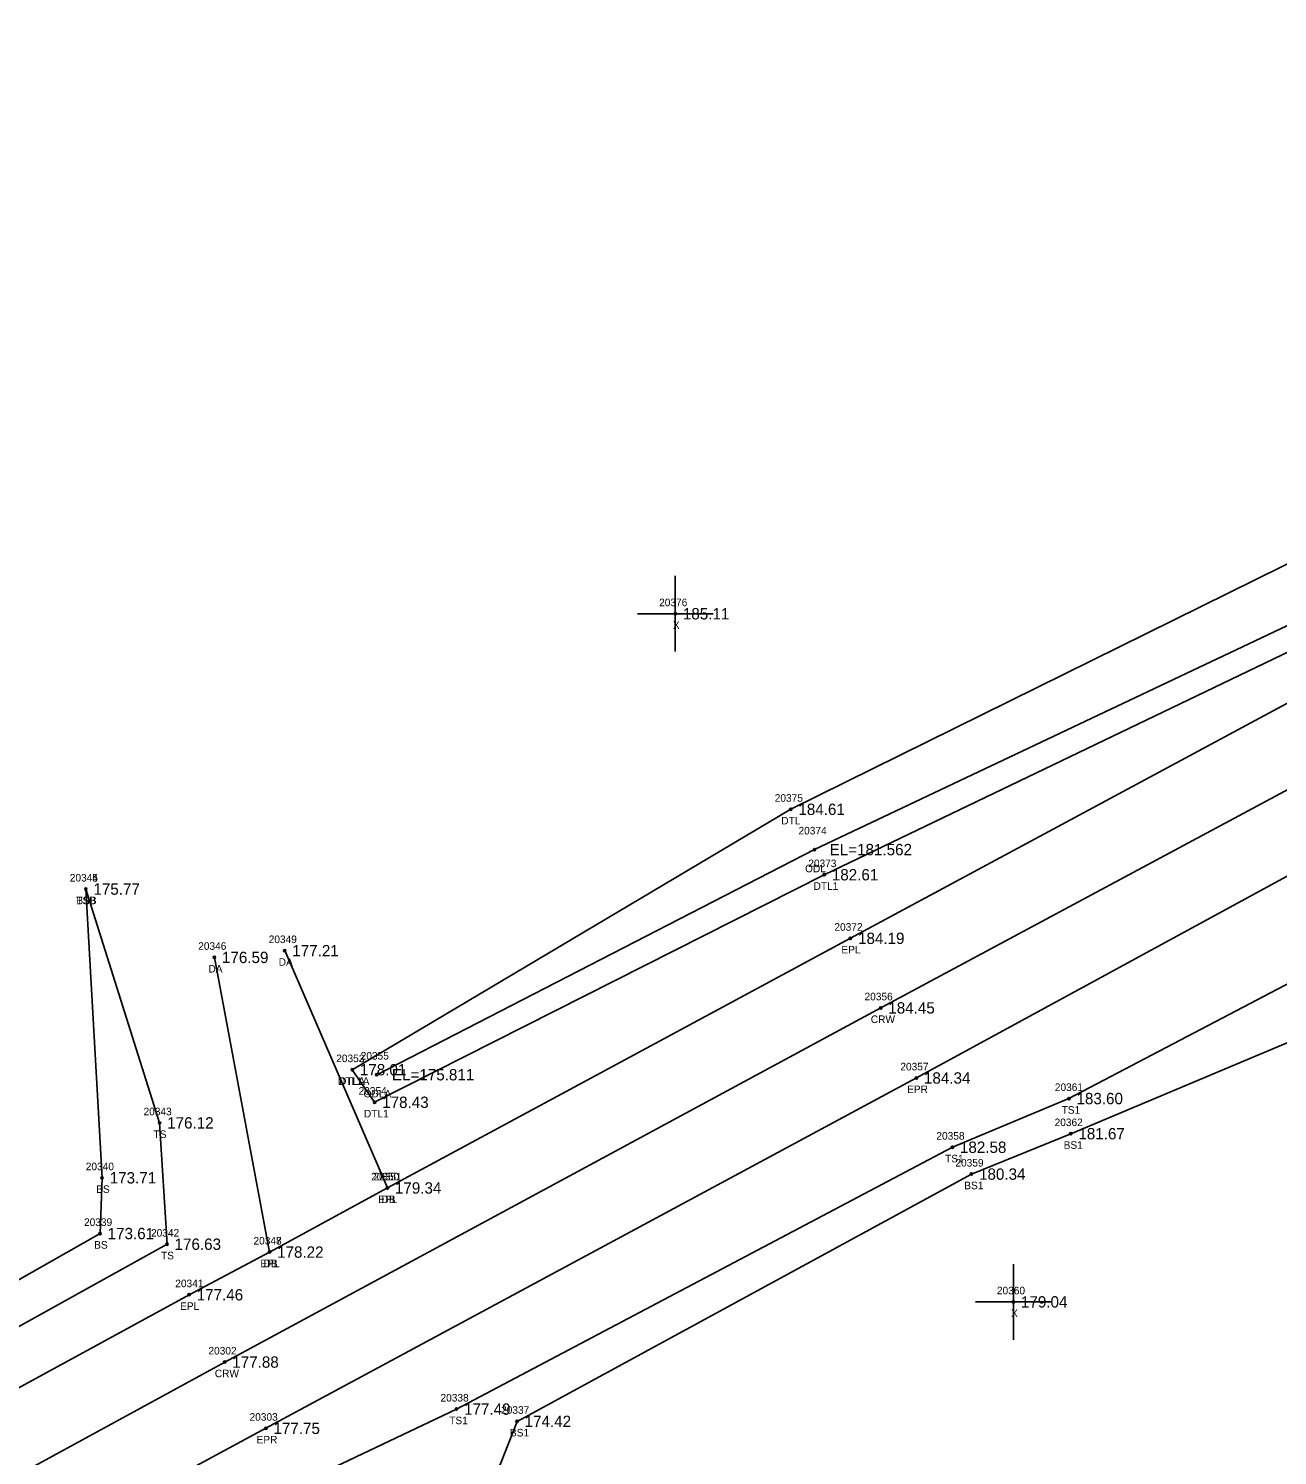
# Model space of a CAD drawing. Extents: x 2279528 to 2280976, y 1061373 to 1062235.
# Drawn here: x 2280628.7 to 2280793.7, y 1062015.3 to 1062203.8 of the extents above; entities that cross this region are included whole.
import ezdxf

# ---------------------------------------------------------------- set-up
doc = ezdxf.new("R2010")
doc.units = 0
for name, color, linetype in [('RD_DTM_BkLn1', 7, 'Continuous'), ('RD_DTM_BkLn2', 7, 'Continuous'), ('RD_DTM_BkLn_txCode', 7, 'Continuous'), ('RD_EX_Driveway', 7, 'Continuous'), ('RD_EX_Driveway_txCode', 7, 'Continuous'), ('RD_EX_H2O', 7, 'Continuous'), ('RD_EX_H2O_txCode', 7, 'Continuous'), ('RD_EX_Misc', 7, 'Continuous'), ('RD_EX_Misc_txCode', 7, 'Continuous'), ('RD_EX_Road', 7, 'Continuous'), ('RD_EX_Road_txCode', 7, 'Continuous'), ('RD_EX_TX_Driveway_ELEV', 7, 'Continuous'), ('RD_EX_TX_H2O_ELEV', 7, 'Continuous'), ('RD_EX_TX_Misc_ELEV', 7, 'Continuous'), ('RD_EX_TX_Road_ELEV', 7, 'Continuous'), ('RD_HC_Survey_ELEV', 7, 'Continuous'), ('RD_HC_Survey_txCode', 7, 'Continuous'), ('RD_SMD_Locator', 7, 'Continuous')]:
    doc.layers.add(name, color=color, linetype=linetype)

msp = doc.modelspace()

# ---------------------------------------------------------------- linework, layer by layer
at = {"layer": 'RD_DTM_BkLn1'}
msp.add_lwpolyline([(2279559.79, 1061433.13), (2279641.23, 1061477.49), (2279727.93, 1061524.84), (2279814.76, 1061571.75), (2279901.26, 1061618.64), (2279982.8, 1061662.56), (2280064.7, 1061706.86), (2280148.08, 1061751.86), (2280234.22, 1061798.46), (2280310.96, 1061840.01), (2280397.69, 1061887.57), (2280487.27, 1061936.5), (2280573.03, 1061983.12), (2280654.64, 1062027.66), (2280741.28, 1062074.45), (2280833.39, 1062123.87), (2280892.52, 1062155.9), (2280939.46, 1062181.85)], dxfattribs=at)
at = {"layer": 'RD_DTM_BkLn2'}
for points in [[(2280244.17, 1061836.72), (2280279.92, 1061859.99), (2280384.06, 1061910.85), (2280474.95, 1061958.02), (2280563.04, 1062001.93), (2280638.18, 1062044.64), (2280638.45, 1062052), (2280636.3, 1062090.14)], [(2280254.15, 1061833.04), (2280297.35, 1061859.31), (2280389.94, 1061901.4), (2280479.75, 1061950.78), (2280565.23, 1061997.82), (2280647.02, 1062043.23), (2280646.04, 1062059.26), (2280636.3, 1062090.14)], [(2280272.88, 1061795.9), (2280297.58, 1061791.78), (2280309.49, 1061810.68), (2280320.64, 1061820.76), (2280406.65, 1061872.9), (2280496.79, 1061919.98), (2280582.43, 1061964.41), (2280663.95, 1062011.32), (2280685.25, 1062021.45), (2280750.74, 1062056.04), (2280766.13, 1062062.47), (2280799.22, 1062079.83)], [(2280270.02, 1061790.74), (2280279.94, 1061788.98), (2280298.7, 1061789.36), (2280312.74, 1061804.74), (2280323.13, 1061815.81), (2280411.42, 1061866.03), (2280499.93, 1061915.08), (2280584.56, 1061957.49), (2280666.91, 1062006.18), (2280674.46, 1062011.72), (2280685.18, 1062009.25), (2280689.93, 1062011.32), (2280693.25, 1062019.83), (2280753.26, 1062052.49), (2280766.38, 1062057.83), (2280800.29, 1062072.08)]]:
    msp.add_lwpolyline(points, dxfattribs=at)
at = {"layer": 'RD_EX_Driveway'}
for p, q in [((2280653.28, 1062081.12), (2280660.56, 1062042.19)), ((2280662.57, 1062082.01), (2280676.12, 1062050.66))]:
    msp.add_line(p, q, dxfattribs=at)
at = {"layer": 'RD_EX_H2O'}
for points in [[(2280671.49, 1062066.28), (2280729.4, 1062100.68), (2280823.37, 1062147.12), (2280881.44, 1062177.57), (2280928.45, 1062203.82)], [(2280674.72, 1062065.62), (2280732.53, 1062095.36), (2280825.67, 1062139.48), (2280884.68, 1062169.76), (2280932.06, 1062197.02)], [(2280671.49, 1062066.28), (2280674.44, 1062061.98), (2280733.82, 1062092.04), (2280826.76, 1062136.68), (2280885.73, 1062168.41), (2280932.89, 1062194.62)]]:
    msp.add_lwpolyline(points, dxfattribs=at)
at = {"layer": 'RD_EX_Misc'}
for p, q in [((2280714.15, 1062121.51), (2280714.15, 1062131.51)), ((2280709.15, 1062126.51), (2280719.15, 1062126.51)), ((2280758.8, 1062030.61), (2280758.8, 1062040.61)), ((2280753.8, 1062035.61), (2280763.8, 1062035.61))]:
    msp.add_line(p, q, dxfattribs=at)
at = {"layer": 'RD_EX_Road'}
for points in [[(2279554.31, 1061441.46), (2279636.61, 1061486.51), (2279673.46, 1061506.76), (2279683.06, 1061512.21), (2279723.14, 1061533.54), (2279809.28, 1061580.29), (2279896.91, 1061627.91), (2279977.07, 1061671.02), (2280059.64, 1061715.57), (2280142.91, 1061760.72), (2280228.83, 1061807.06), (2280306.04, 1061849.18), (2280392.98, 1061896.71), (2280482.82, 1061945.75), (2280567.83, 1061991.78), (2280649.94, 1062036.55), (2280660.56, 1062042.19), (2280676.12, 1062050.66), (2280737.28, 1062083.64), (2280828.54, 1062132.77), (2280887.86, 1062164.61), (2280934.91, 1062190.9)], [(2280403.05, 1061879.04), (2280492, 1061927.92), (2280577.25, 1061974.17), (2280660.08, 1062018.91), (2280745.99, 1062065.19), (2280838.21, 1062115.39), (2280896.66, 1062146.92), (2280943.94, 1062172.8)]]:
    msp.add_lwpolyline(points, dxfattribs=at)
at = {"layer": 'RD_SMD_Locator'}
for centre in [(2280714.15, 1062126.51), (2280729.4, 1062100.68), (2280732.53, 1062095.36), (2280733.82, 1062092.04), (2280636.3, 1062090.14), (2280636.3, 1062090.14), (2280737.28, 1062083.64), (2280653.28, 1062081.12), (2280662.57, 1062082.01), (2280741.28, 1062074.45), (2280671.49, 1062066.28), (2280671.49, 1062066.28), (2280674.72, 1062065.62), (2280745.99, 1062065.19), (2280674.44, 1062061.98), (2280766.13, 1062062.47), (2280646.04, 1062059.26), (2280766.38, 1062057.83), (2280750.74, 1062056.04), (2280638.45, 1062052), (2280753.26, 1062052.49), (2280676.12, 1062050.66), (2280676.12, 1062050.66), (2280638.18, 1062044.64), (2280647.02, 1062043.23), (2280660.56, 1062042.19), (2280660.56, 1062042.19), (2280649.94, 1062036.55), (2280758.8, 1062035.61), (2280654.64, 1062027.66), (2280685.25, 1062021.45), (2280660.08, 1062018.91), (2280693.25, 1062019.83)]:
    msp.add_circle(centre, 0.15, dxfattribs=at)

# ---------------------------------------------------------------- texts
at = {"layer": 'RD_DTM_BkLn_txCode'}
for s, p in [('20344', (2280634.18, 1062091.14)), ('20345', (2280634.18, 1062091.14)), ('TSB', (2280635.03, 1062088.14)), ('BSB', (2280635.05, 1062088.14)), ('20361', (2280764.27, 1062063.47)), ('TS1', (2280765.17, 1062060.47)), ('20343', (2280643.92, 1062060.26)), ('20362', (2280764.24, 1062058.83)), ('TS', (2280645.24, 1062057.26)), ('20358', (2280748.63, 1062057.04)), ('BS1', (2280765.44, 1062055.83)), ('20340', (2280636.29, 1062053)), ('TS1', (2280749.78, 1062054.04)), ('20359', (2280751.14, 1062053.49)), ('BS', (2280637.67, 1062050)), ('BS1', (2280752.31, 1062050.49)), ('20339', (2280636.06, 1062045.64)), ('20342', (2280644.91, 1062044.23)), ('BS', (2280637.4, 1062042.64)), ('TS', (2280646.23, 1062041.23)), ('20338', (2280683.14, 1062022.45)), ('TS1', (2280684.29, 1062019.45)), ('20337', (2280691.14, 1062020.83)), ('BS1', (2280692.31, 1062017.83))]:
    msp.add_text(s, height=1, dxfattribs=at).set_placement(p)
at = {"layer": 'RD_EX_Driveway_txCode'}
for s, p in [('20346', (2280651.14, 1062082.12)), ('20349', (2280660.45, 1062083.01)), ('DA', (2280661.77, 1062080.01)), ('DA', (2280652.49, 1062079.12)), ('20350', (2280673.97, 1062051.66)), ('DB', (2280675.34, 1062048.66)), ('20347', (2280658.44, 1062043.19)), ('DB', (2280659.78, 1062040.19))]:
    msp.add_text(s, height=1, dxfattribs=at).set_placement(p)
at = {"layer": 'RD_EX_H2O_txCode'}
for s, p in [('20375', (2280727.28, 1062101.68)), ('DTL', (2280728.15, 1062098.68)), ('20374', (2280730.42, 1062097.36)), ('20373', (2280731.71, 1062093.04)), ('ODL', (2280731.29, 1062092.36)), ('DTL1', (2280732.41, 1062090.04)), ('20352', (2280669.37, 1062067.28)), ('20353', (2280669.37, 1062067.28)), ('20355', (2280672.6, 1062067.62)), ('DTL1A', (2280669.59, 1062064.28)), ('DTLA', (2280669.75, 1062064.28)), ('20354', (2280672.32, 1062062.98)), ('ODLA', (2280672.98, 1062062.62)), ('DTL1', (2280673.03, 1062059.98))]:
    msp.add_text(s, height=1, dxfattribs=at).set_placement(p)
at = {"layer": 'RD_EX_Misc_txCode'}
for s, p in [('20376', (2280712.01, 1062127.51)), ('X', (2280713.83, 1062124.51)), ('20360', (2280756.62, 1062036.61)), ('X', (2280758.49, 1062033.61))]:
    msp.add_text(s, height=1, dxfattribs=at).set_placement(p)
at = {"layer": 'RD_EX_Road_txCode'}
for s, p in [('20372', (2280735.16, 1062084.64)), ('EPL', (2280736.08, 1062081.64)), ('20357', (2280743.87, 1062066.19)), ('EPR', (2280744.76, 1062063.19)), ('20351', (2280674.29, 1062051.66)), ('EPL', (2280674.92, 1062048.66)), ('20348', (2280658.44, 1062043.19)), ('EPL', (2280659.35, 1062040.19)), ('20341', (2280648.11, 1062037.55)), ('EPL', (2280648.74, 1062034.55)), ('20303', (2280657.92, 1062019.91)), ('EPR', (2280658.85, 1062016.91))]:
    msp.add_text(s, height=1, dxfattribs=at).set_placement(p)
at = {"layer": 'RD_EX_TX_Driveway_ELEV'}
for s, p in [('177.21', (2280663.57, 1062081.26)), ('176.59', (2280654.28, 1062080.37)), ('179.34', (2280677.12, 1062049.91)), ('178.22', (2280661.56, 1062041.44))]:
    msp.add_text(s, height=1.5, dxfattribs=at).set_placement(p)
at = {"layer": 'RD_EX_TX_H2O_ELEV'}
for s, p in [('184.61', (2280730.4, 1062099.93)), ('EL=181.562', (2280734.53, 1062094.61)), ('182.61', (2280734.82, 1062091.29)), ('178.01', (2280672.49, 1062065.53)), ('178.01', (2280672.49, 1062065.53)), ('EL=175.811', (2280676.72, 1062064.87)), ('178.43', (2280675.44, 1062061.23))]:
    msp.add_text(s, height=1.5, dxfattribs=at).set_placement(p)
at = {"layer": 'RD_EX_TX_Misc_ELEV'}
for s, p in [('185.11', (2280715.15, 1062125.76)), ('175.77', (2280637.3, 1062089.39)), ('175.77', (2280637.3, 1062089.39)), ('183.60', (2280767.13, 1062061.72)), ('176.12', (2280647.04, 1062058.51)), ('181.67', (2280767.38, 1062057.08)), ('182.58', (2280751.74, 1062055.29)), ('173.71', (2280639.45, 1062051.25)), ('180.34', (2280754.26, 1062051.74)), ('173.61', (2280639.18, 1062043.89)), ('176.63', (2280648.02, 1062042.48)), ('179.04', (2280759.8, 1062034.86)), ('177.49', (2280686.25, 1062020.7)), ('174.42', (2280694.25, 1062019.08))]:
    msp.add_text(s, height=1.5, dxfattribs=at).set_placement(p)
at = {"layer": 'RD_EX_TX_Road_ELEV'}
for s, p in [('184.19', (2280738.28, 1062082.89)), ('184.34', (2280746.99, 1062064.44)), ('179.34', (2280677.12, 1062049.91)), ('178.22', (2280661.56, 1062041.44)), ('177.46', (2280650.94, 1062035.8)), ('177.75', (2280661.08, 1062018.16))]:
    msp.add_text(s, height=1.5, dxfattribs=at).set_placement(p)
at = {"layer": 'RD_HC_Survey_ELEV'}
for s, p in [('184.45', (2280742.28, 1062073.7)), ('177.88', (2280655.64, 1062026.91))]:
    msp.add_text(s, height=1.5, dxfattribs=at).set_placement(p)
at = {"layer": 'RD_HC_Survey_txCode'}
for s, p in [('20356', (2280739.14, 1062075.45)), ('CRW', (2280739.97, 1062072.45)), ('20302', (2280652.49, 1062028.66)), ('CRW', (2280653.33, 1062025.66))]:
    msp.add_text(s, height=1, dxfattribs=at).set_placement(p)

doc.saveas('drawing.dxf')
